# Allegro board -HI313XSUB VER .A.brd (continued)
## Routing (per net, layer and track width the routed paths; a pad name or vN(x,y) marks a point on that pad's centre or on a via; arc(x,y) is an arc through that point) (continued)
VINNQ: length 4.1
  TOP w0.203: 21.16,40.77 21.33,40.6 U25.36
  TOP w0.508: 21.16,40.77 20.82,41.11 20.82,42.76 C299.1 C267.1
VINPQ: length 3.9
  TOP w0.203: U25.35 21.73,41.15
  TOP w0.508: 21.73,41.15 21.48,41.41 21.48,42.85 C300.1 C266.1
3130_AGC: length 2.3
  TOP w0.203: R43.2 94.35,36.77 94.35,36.69 93.93,36.27 U5.7
3130_I2C_SCL: length 29.8
  TOP w0.152: R8.1 80.51,38.63 77.32,38.63 75.68,40.27 75.68,50.99 J7.23
3130_I2C_SDA: length 34.2
  TOP w0.152: J7.24 65.02,61.23 67.11,61.23 67.61,60.72 67.61,59.53 75.98,51.16 75.98,40.4 77.44,38.93 79.72,38.93 R9.1
3130_RSTN: length 26
  TOP w0.152: R30.1 77.58,27.1 67.54,37.15 67.54,40.61 67.03,41.12 65.23,41.12 J7.10
3130_TSI_CLK: length 28.6
  TOP w0.152: J7.19 67.52,55.09 73.55,49.05 73.55,39.94 77.1,36.39 79.85,36.39 80,36.24 C71.2 80.51,35.83 80.52,35.84 RN1.6
3130_TSI_D0: length 43.8
  TOP w0.152: RN3.8 76.16,29.01 67.84,37.32 67.84,40.84 67.51,41.17 67.51,43.2 67.16,43.55 v1(62.2,43.55)
  BOTTOM w0.152: v1(62.2,43.55) 61.36,44.39 61.36,52.22 62.88,53.74 65.3,53.74 J7.17
3130_TSI_D1: length 39.5
  TOP w0.152: v1(62.43,46.12) 67.38,46.12 68.12,45.38 68.12,42.69 68.55,42.26 68.55,38.14 76.55,30.14 80.34,30.14 80.97,29.51 RN3.7
  BOTTOM w0.152: J7.15 65.02,51.48 63.24,51.48 62.43,50.67 v1(62.43,46.12)
3130_TSI_D2: length 30.9
  TOP w0.152: v1(67.99,46.91) 68.45,46.45 68.45,42.79 68.85,42.39 68.85,38.3 76.7,30.45 80.54,30.45 80.97,30.02 RN3.6
  BOTTOM w0.152: J7.16 65.38,48.58 67.2,48.58 67.99,47.8 v1(67.99,46.91)
3130_TSI_D3: length 27.1
  TOP w0.152: RN3.5 80.98,30.53 80.04,31.48 77.15,31.48 69.64,38.98 69.64,42.87 69.23,43.27 69.23,46.98 67.99,48.23 67.26,48.23 J7.13
3130_TSI_D4: length 29.8
  TOP w0.152: J7.14 65.25,48.76 67.99,48.76 69.61,47.14 69.61,43.38 69.94,43.05 69.94,39.13 77.29,31.79 80.47,31.79 80.98,32.31 RN2.7
3130_TSI_D5: length 22.3
  TOP w0.152: RN2.6 77.74,32.82 70.61,39.95 v1(70.61,43.76)
  BOTTOM w0.152: v1(70.61,43.76) 69.44,44.93 J7.11
3130_TSI_D6: length 26
  TOP w0.152: RN2.5 77.66,33.32 71.11,39.87 71.11,44.37 v1(70.55,44.93)
  BOTTOM w0.152: v1(70.55,44.93) 69.39,46.09 65.12,46.09 J7.12
3130_TSI_D7: length 18.8
  TOP w0.152: RN1.8 77.27,34.83 72.23,39.87 72.23,41.04 v1(72.03,41.24)
  BOTTOM w0.152: J7.9 70.88,42.39 v1(72.03,41.24)
3130_TSI_SYNC: length 31.7
  TOP w0.152: RN1.5 81.37,36.35 80.29,37.44 77.52,37.44 74.62,40.33 74.62,49.44 67.63,56.43 65.15,56.43 J7.22
3130_TSI_VALID: length 31.1
  TOP w0.152: RN1.7 80.57,35.34 80.49,35.25 77.29,35.25 72.54,40.01 72.54,48.41 v1(68.59,52.36)
  BOTTOM w0.152: v1(68.59,52.36) 68.59,55.54 J7.21
3136_ADDR0: length 5
  TOP w0.152: U2.39 137.97,38.84 137.97,38.84 137.62,38.84 137.52,38.94 136.85,38.94 136.2,39.59 136.2,41.17 R41.1
3136_ADDR1: length 2.2
  TOP w0.203: U2.38 138.29,39.24 137.86,39.24 137.63,39.47 v1(137.11,39.47)
  BOTTOM w0.381: R103.1 136.85,39.22 v1(137.11,39.47)
3136_DISEQC_IN: length 38.1
  TOP w0.152: R51.1 163.38,43.61 163.05,43.27 R116.1 162.11,42.16 Q6.3 160.54,42.61 159.42,43.73 159.42,45.05 159.06,45.41 156.45,45.41 155.66,44.62 155.66,39.99 154.64,38.97 154.64,33.31 152.12,30.78 149,30.78 146.79,32.99 146.16,32.99 145.17,33.98 145.17,34.68 144.61,35.24 U2.13
3136_DISEQC_OUT: length 32.7
  TOP w0.152: U2.12 143.37,34.36 143.65,34.08 144.56,34.08 146,32.64 146.68,32.64 148.87,30.46 152.24,30.46 v1(155.2,33.42) ; U17.9 162.5,25.07 162.67,25.24 163.23,25.24 163.38,25.09 163.38,24.48 R123.1 v1(163.97,23.08)
  BOTTOM w0.152: v1(155.2,33.42) 163.97,24.66 v1(163.97,23.08)
3136_FUNC_SEL: length 2.8
  TOP w0.152: U2.14 144.85,35.64 R4.1
3136_HV_SEL: length 33
  TOP w0.152: U2.18 145.72,37.24 145.98,37.51 147.86,37.51 148.32,37.05 148.32,32.51 149.42,31.4 151.48,31.4 v1(151.67,31.59) ; v1(163.27,21.76) 163.27,20.05 162.5,19.28 U17.8
  BOTTOM w0.152: v1(151.67,31.59) 155.04,31.59 162.76,23.87 162.76,22.27 v1(163.27,21.76)
3136_I2C_SCL: length 32.3
  TOP w0.152: U2.41 137.42,38.04 137.23,38.23 136.64,38.23 136.18,37.76 R108.2 C221.1 135.47,39.13 135.34,39.26 133.43,39.26 133.08,39.62 133.08,48.18 127.82,53.44 127.82,57.87 125.53,60.17 J3.23
3136_I2C_SDA: length 34.2
  TOP w0.152: U2.40 137.52,38.44 137.38,38.59 136.65,38.59 R104.2 C217.1 135.47,41.17 135.26,41.37 133.64,41.37 133.38,41.62 133.38,48.3 128.13,53.56 128.13,58.11 124.98,61.26 122.49,61.26 J3.24
3136_IOUT_N: length 29.9
  TOP w0.165: U2.32 140.57,40.72 140.68,40.83 140.68,46.59 140.29,46.98 135.12,52.15 135.12,63.11 136.97,64.95 138.39,64.95 C307.2
3136_IOUT_P: length 29.4
  TOP w0.165: U2.31 140.97,46.71 135.42,52.27 135.42,62.99 137.09,64.66 138.38,64.66 C303.2
3136_LNB_EN: length 42.7
  TOP w0.152: U2.21 145.63,38.44 146.24,37.84 148.04,37.84 148.65,37.23 148.65,32.68 149.41,31.92 v1(150.83,31.92) ; U17.5 160.55,17.58 161.24,16.89 163.07,16.89 164.06,17.87 165.23,17.87 165.74,18.38 v1(165.74,21.58)
  BOTTOM w0.152: v1(150.83,31.92) 151.06,32.15 155.02,32.15 163.08,24.1 163.08,22.72 163.83,21.96 165.35,21.96 v1(165.74,21.58)
3136_QOUT_N: length 32.6
  TOP w0.165: C186.2 138.39,67.45 137.47,67.45 133.89,63.87 133.89,51.56 139.32,46.13 139.32,41.03 139.37,40.98 U2.35
3136_QOUT_P: length 33.1
  TOP w0.165: U2.36 138.97,40.98 139.03,41.03 139.03,46.01 133.6,51.43 133.6,64 137.35,67.74 138.39,67.74 C306.2
3136_RF_AGC: length 31.1
  TOP w0.305: R127.2 C37.1 135.14,44.88 134.65,45.36 134.65,48.69 132.36,50.98 132.36,64.58 137.09,69.31 R60.1
3136_RSTN: length 69.1
  TOP w0.152: v1(155.02,49.04) 155.33,48.74 155.33,40.21 154.34,39.22 154.34,33.48 151.94,31.08 149.21,31.08 147.94,32.35 147.94,34.49 147.71,34.72 146.49,34.72 146.31,34.89 R83.1 C38.1 145.8,36.26 145.58,36.04 U2.15
  BOTTOM w0.152: v1(155.02,49.04) 153.7,50.36 132.82,50.36 126.17,43.7 122.71,43.7 J3.10
3136_TS_CLK: length 3.7
  TOP w0.152: R10.2 137.68,36.04 U2.46
3136_TS_OUT0: length 3.8
  TOP w0.152: U2.48 137.87,35.24 R13.2
3136_TS_OUT1: length 3.1
  TOP w0.152: R12.2 137.57,33.24 137.85,33.24 138.97,34.36 U2.1
3136_TS_OUT2: length 2.7
  TOP w0.152: R14.2 138.33,32.98 138.33,33.11 139.37,34.15 139.37,34.24 139.37,34.25 U2.2
3136_TS_OUT3: length 2.4
  TOP w0.152: U2.3 139.77,34.03 138.9,33.16 R16.2
3136_TS_OUT4: length 2.3
  TOP w0.152: R19.2 140.44,33.08 140.44,33.69 140.57,33.83 140.57,34.56 U2.5
3136_TS_OUT5: length 2.1
  TOP w0.152: U2.6 140.97,33.72 140.88,33.63 R20.2
3136_TS_OUT6: length 2.2
  TOP w0.152: U2.8 141.77,33.8 141.94,33.63 141.94,33.62 142.06,33.51 142.06,32.72 R21.2
3136_TS_OUT7: length 2.3
  TOP w0.152: U2.9 142.17,34.15 142.17,34.15 142.17,33.9 142.88,33.19 R25.2
3136_TS_SYNC: length 3
  TOP w0.152: R226.2 136.31,36.77 136.7,37.16 137.74,37.16 137.82,37.24 U2.43
3136_TS_VAL: length 4.2
  TOP w0.152: U2.44 136.89,36.84 135.83,35.78 C176.1 R5.2
3136_TSI_CLK: length 25.7
  TOP w0.152: R10.1 134.29,34.19 134.29,34.24 130.74,37.79 130.74,47.11 125.4,52.45 125.4,53.62 J3.19
3136_TSI_D0: length 24.4
  TOP w0.152: R13.1 134.25,32.84 129.73,37.36 129.73,46.55 123.93,52.34 J3.17
3136_TSI_D1: length 25.9
  TOP w0.152: J3.15 125.78,50.01 129.42,46.37 129.42,37.18 134.35,32.25 135.82,32.25 136.36,31.72 R12.1
3136_TSI_D2: length 29.1
  TOP w0.152: J3.16 122.82,48.58 124.36,48.58 128.38,44.56 128.38,36.75 133.92,31.21 137.37,31.21 R14.1
3136_TSI_D3: length 26.8
  TOP w0.152: R16.1 138.07,30.89 133.75,30.89 128.05,36.59 128.05,44.43 125.02,47.47 J3.13
3136_TSI_D4: length 30.8
  TOP w0.152: R19.1 138.03,29.86 133.31,29.86 127.02,36.15 127.02,43.44 124.42,46.04 122.82,46.04 J3.14
3136_TSI_D5: length 28.5
  TOP w0.152: J3.11 125.1,44.93 126.7,43.33 126.7,36.04 133.21,29.53 138.13,29.53 139.78,31.18 140.34,31.18 R20.1
3136_TSI_D6: length 32.5
  TOP w0.152: J3.12 122.84,43.48 124.37,43.48 125.69,42.16 125.69,35.58 132.76,28.51 138.66,28.51 R21.1
3136_TSI_D7: length 30.1
  TOP w0.152: R25.1 142.3,31.13 141.71,31.13 138.77,28.19 132.61,28.19 125.36,35.44 125.36,41.95 124.93,42.39 J3.9
3136_TSI_SYNC: length 30
  TOP w0.152: J3.22 122.44,58.67 124.47,58.67 126.78,56.36 126.78,53 132.06,47.72 132.06,38.8 134.09,36.77 R226.1
3136_TSI_VALID: length 27.9
  TOP w0.152: R5.1 133.39,36.08 133.39,36.97 131.76,38.6 131.76,47.56 126.45,52.87 126.45,56.2 125.02,57.63 J3.21
3136_XIN: length 12.6
  TOP w0.203: U2.23 144.64,39.24 145.34,39.95 146.16,39.95 146.52,40.3 R24.1
  TOP w0.254: R24.1 147.1,40.35 C172.1 151.11,40.35 151.59,40.83 X6.2
3136_XOUT: length 12.3
  TOP w0.203: U2.22 144.85,38.84 145.5,39.49 R24.2
  TOP w0.254: X6.1 151.59,39.53 151.26,39.86 148.66,39.86 C174.1 147.94,39.49 R24.2
3137_ADDR0: length 3
  TOP w0.203: U25.40 19.97,38.18 19.6,38.55 19.06,38.55
  TOP w0.381: R209.1 18.68,38.93 19.06,38.55
3137_ADDR1: length 3
  TOP w0.203: U25.38 20.21,38.98 19.71,39.48 19.71,39.71
  TOP w0.381: R208.1 19.71,40.57 19.71,39.71
3137_FUNC_SEL: length 2.4
  TOP w0.203: U25.14 26.86,35.38 27.33,34.92 27.76,34.92 28.03,34.64 R205.1
3137_I2C_SCL: length 28.3
  TOP w0.152: J4.23 14.95,54.27 14.95,36.82 v1(15.41,36.37) 15.89,35.88 R81.1
  BOTTOM w0.152: v1(15.41,36.37) 15.63,36.37 R81.1
3137_I2C_SDA: length 31.5
  TOP w0.152: J4.24 7.61,61.26 9.41,61.26 10.31,60.36 10.31,59.39 15.25,54.45 15.25,37.28 v1(15.46,37.08) 15.63,36.9 R80.1
  BOTTOM w0.152: v1(15.46,37.08) 15.43,37.08 15.61,36.9 R207.2
3137_IF_AGC: length 23.3
  TOP w0.305: R196.1 18.84,63.98 15.41,60.55 15.41,55.49 16.93,53.97 C268.1 16.93,45.88 16.99,45.81 16.99,44.58 R199.2
3137_RSTN: length 51.9
  TOP w0.203: U25.15 26.97,35.78 27.47,35.27 29.88,35.27 30.49,34.66 v1(30.49,34.41) ; J4.10 4.53,40.4 4.53,29.89 5.17,29.25 R198.1 6.54,29.25 6.55,29.24 C340.1 7.7,29.24 v1(8.57,28.37)
  BOTTOM w0.203: v1(30.49,34.41) 30.49,28.09 29.6,27.2 9.74,27.2 v1(8.57,28.37)
3137_TSI_CLK: length 27.9
  TOP w0.152: R133.1 17.26,31.13 13.32,35.07 13.32,50.82 J4.19
3137_TSI_D0: length 27.6
  TOP w0.152: J4.17 12.31,49.29 12.31,34.61 16.3,30.63 18.3,30.63 R134.1
3137_TSI_D1: length 26.6
  TOP w0.152: R165.1 18.99,30.32 16.16,30.32 12,34.48 12,47.06 J4.15
3137_TSI_D2: length 30.2
  TOP w0.152: R227.1 19.67,30.02 16,30.02 11.68,34.33 11.68,46.54 9.36,48.86 7.66,48.86 J4.16
3137_TSI_D3: length 27.1
  TOP w0.152: J4.13 11.35,45.17 11.35,34.2 15.85,29.7 20.32,29.7 R228.1
3137_TSI_D4: length 30.9
  TOP w0.152: J4.14 7.84,46.15 9.93,46.15 11.03,45.05 11.03,34.06 15.72,29.37 20.96,29.37 R230.1
3137_TSI_D5: length 27.5
  TOP w0.152: R231.1 21.59,29.06 15.57,29.06 10.71,33.92 10.71,43.27 J4.11
3137_TSI_D6: length 31
  TOP w0.152: R232.1 22.23,28.73 15.45,28.73 10.4,33.78 10.4,42.56 9.34,43.63 8.85,43.63 7.56,44.93 J4.12
3137_TSI_D7: length 28
  TOP w0.152: R233.1 22.87,28.42 15.32,28.42 10.1,33.63 10.1,41.34 J4.9
3137_TSI_SYNC: length 31.8
  TOP w0.152: J4.22 7.56,58.67 10.01,58.67 14.64,54.03 14.64,36.06 16.75,33.95 R128.1
3137_TSI_VALID: length 28.9
  TOP w0.152: J4.21 10.54,57.63 14.34,53.83 14.34,35.73 R132.1
3137_XIN: length 27.6
  TOP w0.203: R164.2 29.15,40.23 28.46,39.54 27.45,39.54 26.88,38.98 U25.23
  TOP w0.254: R47.1 30.62,43.78 29.88,43.05 R164.2 30.77,40.23 C325.2 34.18,40.35 34.96,41.14 X3.2
3137_XOUT: length 12.4
  TOP w0.203: U25.22 26.99,38.58 27.57,39.16 28.72,39.16 28.97,39.41 R164.1
  TOP w0.254: X3.1 34.96,38.53 34.15,39.34 C322.2 30.82,39.41 R164.1
18250B_SCL_T: length 34.3
  TOP w0.152: v1(93.91,54.63) 93.52,54.23 93.52,50.77 99.03,45.26 99.03,34.36 98.36,33.69 R27.2 ; R39.2 R45.1 v1(85.96,54.27)
  BOTTOM w0.152: v1(85.96,54.27) 92.12,54.27 92.35,54.04 93.33,54.04 v1(93.91,54.63)
18250B_SDA_T: length 32.7
  TOP w0.152: v1(85,54.3) R46.1 R40.2 ; v1(92.9,54.63) 93.16,54.37 93.16,50.69 98.72,45.13 98.72,35.27 98.4,34.96 R26.2
  BOTTOM w0.152: v1(92.9,54.63) 86.61,54.63 86.43,54.81 85.5,54.81 v1(85,54.3)
AC2012_SCL_T: length 25.2
  TOP w0.152: R61.2 136.55,59.16 136.55,52.7 143.16,46.09 143.16,44.21 R65.2 142.91,42.38 142.57,42.04 U2.27
AC2012_SDA_T: length 24.3
  TOP w0.152: R62.2 138.12,60.29 136.86,59.03 136.86,52.83 143.47,46.22 143.47,42.99 R66.2 143.42,42.44 142.97,41.99 U2.26
ANT_CTRL/LOCK: length 48
  TOP w0.203: R224.2 R150.2 51.41,52.59 51.41,35.76 v1(51.26,35.6) ; U25.16 27.07,36.18 27.6,35.65 30.14,35.65 33.94,31.85 36.24,31.85 37.89,33.5 v1(46.27,33.5)
  BOTTOM w0.203: v1(51.26,35.6) 49.15,33.5 v1(46.27,33.5)
ANT_POWER: length 22.7
  TOP w0.508: Q11.3 50.23,70.22 R157.2 44.64,72.1 42.33,74.42 C279.1 41.09,79.44 40.68,79.85 36.49,79.85 L13.2
CLK_TU_OUT: length 1.2
  TOP w0.254: R47.2 30.62,55.49 C330.2
DEMO_VIN: length 19.5
  TOP w0.178: U5.12 91.68,38.46 91.61,38.53 91.61,39.16 92.68,40.23 92.68,48.23 89.76,51.15 89.76,54.08 C50.1 89.73,54.8 89.73,55.02 R7.2
DEMO_VIP: length 19.4
  TOP w0.178: U5.13 91.28,38.51 91.31,38.54 91.31,39.29 92.37,40.35 92.37,48.1 89.45,51.02 89.45,54.09 C51.1 89.43,54.74 89.43,55.05 R11.2
I2C_SCL_3130: length 7.3
  TOP w0.152: U5.20 88.48,38.38 87.94,38.91 84.44,38.91 84.31,39.05 C84.1 R23.2 82.28,39.05 82.26,39.06 R8.2
I2C_SDA_3130: length 8.2
  TOP w0.152: R9.2 82.26,40.15 82.28,40.14 R22.2 C72.1 84.65,39.29 88.02,39.29 88.88,38.44 U5.19
IF_OUTN: length 18.8
  TOP w0.508: C335.2 20.64,61.18 19.93,60.47 19.93,51.38 21.45,49.85 21.45,44.8 C266.2
IF_OUTP: length 20
  TOP w0.508: C267.2 20.79,44.82 20.79,49.58 19.25,51.12 19.25,60.75 20.57,62.07 C337.2
LNB_PWR: length 76.8
  TOP w0.381: D27.1 C170.1 C58.1 C104.1 157.98,68.04 157.98,68.93 156.62,68.93 156.62,69.69 157.98,69.69 157.98,70.45 C78.1 155.72,75.58 154.96,75.58 154.96,71.6 154.17,71.6 154.17,75.58 153.41,75.58 153.41,71.6 151.58,71.6 C64.1
  TOP w0.457: D27.1 165.21,66.51 168.56,63.16 168.56,42.59 168.08,42.11 C155.2 D17.2
  TOP w0.508: J16.2 C64.1
LNB_PWR_B: length 52.2
  TOP w0.381: R166.2 138.98,79.22 140.87,79.22 140.87,74.01 141.63,74.01 141.63,81.55 143.6,81.55 C166.1 143.6,76.49 146.43,76.49 C288.1 C287.1 157.5,79.82 159.8,77.52 159.8,70.01 160.4,69.42 D27.2
LOOPTHROUGH: length 8
  TOP w0.381: J16.1 136.6,77.67 R166.1
  TOP w0.508: C283.1 J16.1
LT: length 4.3
  TOP w0.254: 88.77,66.6 U4.3
  TOP w0.483: C66.2 88.77,66.6
MXL603_SCL: length 18.1
  TOP w0.152: R143.2 27.55,54.11 R213.2 27.75,53.88 27.75,52.67 28.08,52.34 28.08,48.71 v1(27.34,47.97) ; U25.26 25.33,40.5 25.52,40.68 26,40.68 26.07,40.61 27.09,40.61 27.34,40.86 27.34,44.29 v1(26.33,45.31)
  BOTTOM w0.152: v1(27.34,47.97) 26.33,46.96 v1(26.33,45.31)
MXL603_SDA: length 17.6
  TOP w0.152: v1(28.11,47.97) 28.39,48.25 28.39,52.5 28.06,52.83 28.06,53.71 R211.2 R137.2 ; U25.24 26.78,39.38 27.47,40.07 27.47,40.48 27.73,40.73 27.73,44.42 26.84,45.31 v1(26.84,45.94)
  BOTTOM w0.152: v1(26.84,45.94) 26.84,46.7 v1(28.11,47.97)
REG2OUT: length 41.4
  TOP w0.203: U34.2 147.16,69.12 147.96,69.92 148.49,69.92 148.49,68.93 148.06,68.5 U34.1 ; v1(143.16,66.69) 143.39,66.93 U34.10 ; U34.25 149.18,66.53 C225.2 ; C414.1 144.68,70.4 145.96,69.13 U34.5
  TOP w0.254: v1(152.3,66.26) 150.97,66.26 C225.2 ; C414.1 144.23,70.48 v1(144,70.71)
  TOP w0.381: 148.49,69.92 C130.1 152.33,69.92 154.33,67.91 v1(154.33,66.13)
  BOTTOM w0.381: v1(154.33,66.13) 154.21,66.26 v1(152.3,66.26) 150.28,64.24 143.82,64.24 143.16,64.91 143.16,65.78 C131.1 143.16,65.8 v1(143.16,66.69) 142.25,67.6 142.25,68.96 v1(144,70.71)
RESET_TUNER: length 31.7
  TOP w0.152: v1(27.8,37.3) 27.8,37.35 27.77,37.38 U25.19 ; 24.42,51.36 C302.1 22.58,51.36 21.68,52.27 21.68,58.57 22.26,59.15 23.53,59.15 24.81,60.42 U20.10 ; 24.42,51.36 24.42,49.24 28.13,45.54 v1(28.13,40.1) ; 24.42,51.36 R225.2
  BOTTOM w0.152: v1(27.8,37.3) 28.26,37.76 28.26,39.97 v1(28.13,40.1)
RF_IN_18250B: length 3.1
  TOP w0.483: J1.2 C56.1
RF_IN_T: length 3.8
  TOP w0.5: C331.1 L13.1 38.38,77.69 J2.2
RF_OUT_18250B: length 5.4
  TOP w0.483: C79.1 81.19,77.41 arc(80.89,77.61) 80.53,77.69 J1.1
RF_OUT_T: length 1.7
  TOP w0.5: J2.1 23.41,77.67 C333.1
RFIN: length 2.4
  TOP w0.254: 89.9,66.59 89.27,65.96 U4.2
  TOP w0.483: 89.9,66.59 90.58,67.28 C65.2
TS_RSTN_DEMO: length 13.9
  TOP w0.152: U5.37 90.88,31.97 90.91,31.93 C53.1 91.05,31.29 91.12,31.29 91.42,30.99 91.42,29.69 89.59,27.86 85,27.86 84.23,27.1 R37.2 R30.2
$3N275: length 5.2
  TOP w0.203: U2.37 138,39.64 137.63,40.01
  TOP w0.305: R127.1 R69.2 137.35,42.46 137.35,40.29 137.63,40.01
$3N304: length 3.6
  TOP w0.203: C226.1 145.4,41.65 144.7,40.95 144.7,39.96 144.39,39.64 U2.24
$3N444: length 3.2
  TOP w0.381: R68.2 138.82,17.11
  vias: v1(137.73,20.28) v1(137.68,19.21) v1(137.8,23.79) v1(137.8,22.75) v1(137.78,21.58) v1(139.83,21.58) v1(139.83,20.31) v1(139.83,19.19) v1(139.86,23.79) v1(139.86,22.75) v1(142.07,23.81) v1(142.07,22.8) v1(142.07,21.55) v1(142.07,20.28) v1(142.07,19.14)
$3N446: length 3.3
  TOP w0.381: R68.1 R141.1 U12.1
$4N322: length 3.8
  TOP w0.203: U34.27 149.85,67.33 C487.2 150.06,66.93 U34.26
$4N324: length 3.1
  TOP w0.203: C168.2 149.51,64.93 149.51,65.63 149.01,66.13 U34.24
$4N325: length 9.3
  TOP w0.203: 148.33,65.02 U34.22 ; U34.21 147.56,63.51 147.69,63.38 C194.1 147.39,62.27 147.16,62.5 U34.20
  TOP w0.254: 148.33,65.02 148.33,63.37 148.74,62.96 C190.1
  TOP w0.381: C194.1 148.74,62.27 C190.1
$4N326: length 8
  TOP w0.152: U34.15 145.16,64.19 144.32,63.36 143.71,63.36 C538.1 141.91,62.06 141.77,62.2 139.89,62.2 139.77,62.07 R61.1
$4N327: length 9.7
  TOP w0.152: U34.16 145.56,64.08 144.51,63.04 143.85,63.04 142.78,61.97 142.78,60.66 142.42,60.29 C534.1 141.91,60.79 141.77,60.93 139.89,60.93 139.77,60.8 R62.1
$4N328: length 3.2
  TOP w0.152: R72.1 144.56,62.66 144.76,62.66 145.96,63.85 U34.17
$4N329: length 12.1
  TOP w0.203: U34.18 146.36,63.68 145.32,62.64 C532.1
  TOP w0.254: C532.1 145.31,62.2 144.81,62.2 144.68,62.07 144.68,57.75 143.41,56.48 X4.1
$4N330: length 12.2
  TOP w0.203: U34.19 146.76,63.51 146.33,63.09 C531.1
  TOP w0.254: C531.1 146.81,62.22 146.97,62.07 146.97,56.86 147.35,56.48 X4.2
$4N331: length 4.1
  TOP w0.152: R59.1 142.52,62.83 143.9,64.21 143.9,65.22 144.01,65.33 U34.14
$4N332: length 6.7
  TOP w0.152: R64.1 139.75,63.36 139.86,63.47 142.65,63.47 143.57,64.39 143.57,65.38 143.92,65.73 U34.13
$4N333: length 6.3
  TOP w0.165: C303.1 139.75,64.12 140.27,64.64 141.46,64.64 141.91,64.19 C537.1 142.35,64.54 142.35,64.55 142.48,64.67 142.85,64.67 143.24,65.07 143.24,65.63 143.77,66.16 143.85,66.16 143.88,66.13 U34.12
$4N334: length 6.3
  TOP w0.165: C307.1 140.32,64.93 141.42,64.93 141.91,65.42 C241.1 142.44,64.97 142.72,64.97 142.95,65.19 142.95,65.75 143.65,66.45 143.85,66.45 143.92,66.53 U34.11
$4N336: length 5.4
  TOP w0.165: C186.1 140.31,67.46 141.44,67.46 141.91,66.98 C535.1 142.39,67.38 143.53,67.38 143.59,67.33 U34.9
$4N337: length 5.4
  TOP w0.165: C306.1 139.75,68.28 140.28,67.75 141.45,67.75 141.91,68.21 C536.1 142.53,67.67 143.53,67.67 143.59,67.73 U34.8
$4N338: length 5
  TOP w0.203: 146.76,69.69 U34.3
  TOP w0.508: L1.2 146.76,72.43 R63.1 146.76,69.69
$4N360: length 1.1
  TOP w0.508: C304.2 146.76,74.33 R63.2
$4N368: length 2.9
  TOP w0.508: C64.2 C305.2 L1.1
$4N406: length 4.7
  TOP w0.152: C148.1 145.29,71.85 145.29,70.33 146.36,69.27 U34.4
$4N416: length 8.1
  TOP w0.152: v1(144.89,69.44) 145.07,69.44 145.56,68.95 U34.6
  TOP w0.305: v1(143.44,68.6) 142.73,69.31 C545.1 141.91,69.81 141.77,69.94 140.09,69.94 139.75,69.61 R60.2
  BOTTOM w0.305: v1(143.44,68.6) 143.78,68.94 144.28,69.44 v1(144.89,69.44)
$4N439: length 3.9
  TOP w0.381: R112.1 166.25,60.93 R2.1 166.96,59.56 166.48,59.07 U14.1
$4N597: length 4.6
  TOP w0.508: C283.2 L16.2 C282.1
$4N600: length 4.7
  TOP w0.203: U34.7 144.94,68.5 arc(144.74,68.54) 144.57,68.65 144.43,68.8
  TOP w0.508: C282.2 142.8,71.48 arc(142.99,70.51) 143.54,69.68 144.43,68.8
$4N809: length 4
  TOP w0.305: C171.2 156.39,17.48 158.24,17.48 158.6,17.84 U17.2
$4N822: length 3.5
  TOP w0.152: C163.2 C175.2 159.98,17.16 159.9,17.25 U17.4
$4N827: length 1
  TOP w0.152: R102.2 C175.1
$4N836: length 4.8
  TOP w0.152: U17.6 161.2,17.58 161.56,17.21 162.94,17.21 163.56,17.83 163.56,18.13 R117.2
$4N838: length 4.5
  TOP w0.152: U17.7 161.85,17.76 162.03,17.57 162.84,17.57 163.07,17.8 163.07,18.7 R121.2
$4N849: length 2
  TOP w0.254: U17.14 159.25,26.2 C139.1
$4N898: length 4.1
  TOP w0.152: R92.1 163.43,25.85 161.7,25.85 161.2,25.34 U17.11
$4N900: length 3.4
  TOP w0.152: C246.1 163.7,25.55 162.03,25.55 161.85,25.36 U17.10
$4N922: length 3.2
  TOP w0.381: R114.1 R51.2 162.85,45.08 Q6.1
$4N925: length 3.6
  TOP w0.381: R35.2 167.11,45.05 165.77,43.71 R114.2 165.64,43.48 C155.1
$5N739: length 4
  TOP w0.381: U21.1 39.56,31.08 R18.1 R50.1
$5N778: length 7.2
  TOP w0.203: 19.17,39.49 20.08,38.58 U25.39
  TOP w0.381: 19.17,39.49 19.17,40.05 18.43,40.79 R216.2 R199.1
$5N783: length 3.8
  TOP w0.152: U25.47 20.26,35.38 18.46,33.57 18.46,33.5 R132.2
$5N784: length 4.3
  TOP w0.152: U25.48 20.43,34.98 18.88,33.43 18.88,33 R133.2
$5N786: length 3.5
  TOP w0.152: U25.46 20.2,35.78 18.38,33.95 R128.2
$5N788: length 4.3
  TOP w0.152: R81.2 17.44,35.88 17.57,35.76 C298.1 18.41,36.19 18.43,36.19 19.17,36.93 20.08,36.93 20.13,36.98 U25.43
$5N863: length 4.1
  TOP w0.152: R134.2 19.72,32.86 20.69,32.86 21.73,33.91 U25.2
$5N867: length 3
  TOP w0.203: U25.32 22.93,41.57
  TOP w0.607: 22.93,41.57 22.93,41.91 23.25,42.23 R204.1
$5N880: length 4.3
  TOP w0.381: R197.1 C345.2 47.11,37.53 v1(46.9,37.74) U18.4
  BOTTOM w0.381: R79.2 47.7,37.74 v1(46.9,37.74)
$5N881: length 2.7
  TOP w0.381: C345.1 47.79,39.58 C224.1
  BOTTOM w0.381: v1(46.7,39.44) R79.1
$5N882: length 24.4
  TOP w0.508: R222.2 41.06,46.45 v1(41.57,46.96)
  BOTTOM w0.381: R201.1 24.54,42.37 26.59,42.37 28.36,44.14 28.36,45.81 32.45,49.9 40.15,49.9 41.57,48.48 v1(41.57,46.96)
$5N900: length 4
  TOP w0.152: R80.2 17.41,36.9 17.59,36.72 C295.1 18.53,36.72 19.06,37.26 19.95,37.26 20.07,37.38 U25.42
$5N935: length 3.5
  TOP w0.152: U25.3 22.13,33.87 20.79,32.53 20.38,32.53 R165.2
$5N944: length 3.1
  TOP w0.152: R227.2 21.22,32.38 21.22,32.53 22.53,33.84 U25.4
$5N946: length 2.8
  TOP w0.152: U25.5 22.93,33.81 21.76,32.63 R228.2
$5N948: length 2.6
  TOP w0.152: R230.2 22.72,33.17 23.33,33.78 U25.6
$5N950: length 2.5
  TOP w0.152: R231.2 24.13,32.42 U25.8
$5N952: length 2.4
  TOP w0.152: U25.9 24.53,32.55 24.63,32.45 R232.2
$5N954: length 2.6
  TOP w0.152: R233.2 24.93,32.6 U25.10
$6N450: length 3.1
  TOP w0.152: Q12.1 v1(50.97,64.33)
  BOTTOM w0.381: R217.1 51.09,64.46 v1(50.97,64.33) 50.94,64.31 R162.2
$6N451: length 5.9
  TOP w0.381: v1(51.09,69.06) 51.22,68.93 Q11.2 51.42,67.71 R200.2
  BOTTOM w0.381: R217.2 v1(51.09,69.06)
$6N454: length 3.2
  TOP w0.152: U20.17 27.97,57.49 28.44,57.02 C252.1 R137.1
$6N455: length 3
  TOP w0.152: U20.16 27.47,56.82 C253.1 R143.1
$6N457: length 12.7
  TOP w0.203: U20.19 29.51,59.42 30.69,58.24 32.58,58.24 32.93,58.59 35.33,58.59 C326.1 38.46,58.58 39.28,57.75 X5.2
$6N458: length 3.7
  TOP w0.5: 28.28,75.93 28.27,75.91 L11.1 ; 28.28,75.93 28.3,75.94 C338.1 arc(28.39,77.28) R167.2 L10.2 ; 28.28,75.93 R169.1
$6N459: length 1.8
  TOP w0.5: L14.1 R169.2 28.27,75.13 L11.2
$6N460: length 2.7
  TOP w0.5: C332.1 32.42,77.69 D1.3 32.68,77.69 C331.2
$6N461: length 1
  TOP w0.5: C338.2 27.48,77.79 L12.1
$6N463: length 3.7
  TOP w0.381: Q11.1 v1(49.19,69.06)
  BOTTOM w0.381: R214.2 49.82,68.42 v1(49.19,69.06)
$6N464: length 1.7
  TOP w0.203: R224.1 48.93,54.98 Q10.1
$6N465: length 1.1
  TOP w0.5: C329.2 R170.1
$6N466: length 3.2
  TOP w0.152: C294.2 31.41,63.09 29.75,61.42 U20.23
$6N467: length 2.7
  TOP w0.254: C330.1 30.14,56.86 28.47,58.54 U20.18
$6N468: length 5.3
  TOP w0.254: R196.2 21.81,63.98 21.83,63.95 C285.1 23.33,63.95 24.24,63.04 25.76,63.04 25.97,62.83 U20.6
$6N470: length 3.8
  TOP w0.254: v1(27.03,64.61) C318.2 ; U20.2 27.97,63.46 v1(28.23,63.72)
  BOTTOM w0.254: v1(28.23,63.72) 27.46,64.5 arc(27.33,64.58) 27.19,64.61 v1(27.03,64.61)
$6N471: length 3.3
  TOP w0.254: C321.2 28.42,65.45 arc(28.33,64.97) 28.05,64.56 27.84,64.34 arc(27.56,63.93) 27.47,63.45 U20.3
$6N487: length 1.8
  TOP w0.5: L10.1 29.45,77.72 R167.1 C332.2
$6N488: length 3
  TOP w0.5: C329.1 D2.3 C333.2
$6N491: length 14.9
  TOP w0.254: U20.24 29.44,61.92 arc(29.6,61.95) 29.73,62.04 29.87,62.19 arc(30.07,62.48) 30.14,62.83 30.14,63.14
  TOP w0.5: 30.14,63.14 v1(30.14,70.2) ; R170.2 v1(25.19,70.2)
  BOTTOM w0.5: v1(25.19,70.2) v1(30.14,70.2)
$6N492: length 17
  TOP w0.203: U20.20 29.54,59.92 30.87,58.6 32.25,58.6 33.16,59.51 C327.1 38.49,59.51 39.28,60.29 X5.1
$6N503: length 6.4
  TOP w0.508: v1(49.95,64.36) Q12.3 Q10.3
  BOTTOM w0.381: v1(49.95,64.36) 49.82,64.48 R214.1
$6N504: length 2.6
  TOP w0.254: C337.1 22.94,61.92 U20.7
$6N505: length 2.7
  TOP w0.254: C335.1 23.05,61.44 25.33,61.44 U20.8
$6N513: length 3
  TOP w0.254: U20.9 24.67,60.92 23.53,59.78 R192.1
$6N515: length 3.5
  TOP w0.254: U20.12 25.08,59.42 24.65,59 C290.1
  TOP w0.381: C290.1 24.4,57.38 LB2.1
$6N592: length 2.3
  TOP w0.5: L14.2 C346.2 28.3,71.66 28.21,71.57 28.22,71.56 Z1.3
$6N593: length 2.4
  TOP w0.5: Z1.2 28.18,69.18 R195.1 28.18,67.2 C321.1
$6N594: length 1.4
  TOP w0.483: Z1.4 27.37,71.55 27.39,71.57 27.39,72.56 R171.1
$6N595: length 2.4
  TOP w0.483: 27.37,69.19 27.37,69.22 Z1.1
  TOP w0.5: 27.37,69.19 R195.2 27.37,67.3 C318.1
$7N202: length 3.3
  TOP w0.381: R17.1 R32.1 77.65,51.08 U3.1
$7N218: length 3.9
  TOP w0.152: R26.1 95.78,34.46 93.49,34.46 93.28,34.67 U5.3
$7N219: length 3.9
  TOP w0.152: U5.2 93.25,34.27 93.39,34.13 95.83,34.13 R27.1
$7N227: length 5.9
  TOP w0.152: U5.25 87.33,35.87 86.69,35.23 84.31,35.23 83.69,35.84 RN1.3
$7N228: length 5.9
  TOP w0.152: U5.22 87.5,37.07 87.18,37.39 84.43,37.39 83.39,36.35 RN1.4
$7N237: length 4.2
  TOP w0.381: 79.7,46.99 R17.2
$7N362: length 4.3
  TOP w0.203: R6.1 93.68,30.66 R31.2 93.67,30.9 92.08,32.49 U5.40
$7N366: length 10.5
  TOP w0.203: U5.39 91.68,32.39 92.86,31.21 R31.1 93.12,30.41 93.12,28.76 C62.1 93.76,28.12 93.76,26.37 92.95,25.56 X1.2
$7N370: length 6
  TOP w0.203: R6.2 C63.1 94.5,28.61 94.14,28.25 94.14,26.37 94.95,25.56 X1.1
$7N391: length 6
  TOP w0.152: RN2.2 83.07,32.31 83.24,32.48 86.13,32.48 87.52,33.87 U5.30
$7N393: length 6
  TOP w0.152: U5.29 87.49,34.27 86.04,32.82 RN2.3
$7N395: length 5.9
  TOP w0.152: RN2.4 86.09,33.32 87.44,34.67 U5.28
$7N397: length 5.8
  TOP w0.152: U5.27 87.4,35.07 86.79,34.47 83.66,34.47 83.29,34.83 RN1.1
$7N399: length 5.8
  TOP w0.152: U5.26 87.37,35.47 86.74,34.85 84.06,34.85 83.57,35.34 RN1.2
$7N402: length 7.3
  TOP w0.152: RN3.4 86.09,30.53 87.87,32.31 87.87,32.5 88.48,33.11 U5.31
$7N404: length 8
  TOP w0.152: U5.32 88.88,32.95 88.2,32.27 88.2,32.08 86.14,30.02 RN3.3
$7N406: length 10.2
  TOP w0.152: U5.34 89.68,32.68 89.45,32.45 89.45,31.99 89.26,31.8 89.26,30.31 88.47,29.51 RN3.2
$7N408: length 11.7
  TOP w0.152: RN3.1 89.42,29.01 90.39,29.98 90.39,31.79 90.57,31.97 90.57,32.56 90.48,32.65 U5.36
$8N5: length 4.2
  TOP w0.483: C48.2 R34.2 90.61,71.75 90.61,70.66 R15.1 C40.1 C6.1
$8N73: length 4.2
  TOP w0.483: C40.2 R15.2 90.61,69.84 C65.1 D3.3
$8N179: length 3.8
  TOP w0.381: R42.1 104.41,35.32 104.23,35.5 R1.1 U1.1
$8N211: length 1.7
  TOP w0.254: U4.30 91.32,63.74
  TOP w0.381: C30.2 92.15,63.74 91.32,63.74
$8N230: length 4.3
  TOP w0.203: U4.26 90.95,61.74 91.24,61.44 91.24,60.42 C31.1
  TOP w0.305: C31.1 R33.1
$8N237: length 24.3
  TOP w0.305: R33.2 92.01,57.35 92.01,50.17 97.2,44.98 97.2,37.56 96.63,36.99 C32.1 R43.1
$8N249: length 1.8
  TOP w0.178: C35.1 89.67,59.3 89.67,59.76 89.77,59.85 U4.24
$8N251: length 1.7
  TOP w0.178: C39.1 89.37,59.13 89.37,59.75 89.27,59.85 U4.23
$8N253: length 2.5
  TOP w0.178: R7.1 89.76,56.55 89.76,56.8 C59.2 90.1,57.14 89.76,57.49 89.76,57.82 C35.2
$8N255: length 2.5
  TOP w0.178: R11.1 89.45,56.52 89.45,56.8 C61.1 89.11,57.14 89.45,57.49 89.45,57.82 C39.2
$8N297: length 5.4
  TOP w0.152: R39.1 C82.1 85.96,58.87 86.42,59.33 87.61,59.33 88.27,59.99 U4.21
$8N299: length 5.6
  TOP w0.152: R40.1 C83.1 85,58.54 86.16,59.71 87.52,59.71 87.77,59.96 U4.20
$8N324: length 2.8
  TOP w0.254: C69.1 82.77,63.24 C2.1 83.82,63.24 U4.12
$8N326: length 3
  TOP w0.254: C70.1 82.86,62.42 C2.2 84.2,62.42 84.52,62.74 U4.13
$8N328: length 7.9
  TOP w0.254: X2.1 78.1,63.61 78.6,63.11 81.72,63.11 C69.2
$8N330: length 8.3
  TOP w0.254: X2.2 78.1,62.01 78.57,62.48 81.69,62.48 C70.2
$8N351: length 4.1
  TOP w0.254: U4.9 84.88,64.74 84.14,65.48 R44.1 82.85,65.48 C76.1 R38.1
$8N354: length 1
  TOP w0.254: R38.2 C44.1
$8N359: length 3
  TOP w0.254: U4.10 84.74,64.24 84.31,64.66 R44.2 82.79,64.66 C77.1
$8N375: length 2.5
  TOP w0.254: U4.8 86.27,65.8 85.96,66.11 85.76,66.31
  TOP w0.381: C41.1 85,66.31 85.76,66.31
$8N396: length 1.1
  TOP w0.483: C6.2 L2.1
$8N403: length 4.5
  TOP w0.483: C85.1 C48.1 R34.1 90.61,72.56 89.64,73.53 C3.2
$8N409: length 1.1
  TOP w0.483: L3.1 C85.2
$8N416: length 3.8
  TOP w0.483: R36.1 89.57,74.61 arc(89.68,74.68) 89.8,74.71 C28.1 ; R36.1 C3.1 ; R36.1 88.71,74.47 arc(88.59,74.64) 88.55,74.84 C49.2
$8N419: length 1.2
  TOP w0.483: C28.2 L15.1
$8N429: length 2.1
  TOP w0.483: C52.2 C49.1 C29.1
$8N432: length 1.2
  TOP w0.483: C29.2 L17.1
$8N437: length 1.2
  TOP w0.483: L4.1 C27.2
$8N439: length 2.3
  TOP w0.483: C80.2 88.55,79.11 C52.1 C27.1
$8N444: length 2.3
  TOP w0.483: L5.1 C56.2 C80.1
$8N472: length 6
  TOP w0.483: C66.1 87.43,71.18 L8.1 87.41,71.19 D4.3 85.69,72.91 85.69,72.91 C79.2

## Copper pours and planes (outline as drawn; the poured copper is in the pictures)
1V1_VDD_T on TOP (solid shape): 40.43,47.08 40.43,45.56 40.3,45.43 39.03,45.43 38.9,45.56 38.9,47.08 39.03,47.21 40.3,47.21
1V1_VDD_T on BOTTOM (solid shape): outline of 108 points within 17.82,31.72 40.3,48.74
1V2_DVDD_S on TOP (solid shape): 132.88,25.24 132.88,23.49 132.82,23.44 131.89,23.44 131.68,23.64 130.49,23.64 130.41,23.72 130.41,25.22 130.56,25.37 132.75,25.37
1V2_DVDD_S on BOTTOM (solid shape): outline of 104 points within 130.41,24.78 148.61,41.56
1V8_T on TOP (solid shape): 51.35,34.51 51.35,28.67 49.7,27.02 47.66,27.02 46.52,28.16 41.31,28.16 41.19,28.29 41.19,29.3 41.31,29.43 46.39,29.43 47.41,30.45 49.19,30.45 49.95,31.21 49.95,34.51 50.08,34.64 51.22,34.64
3V3_C on TOP (solid shape): 104.05,50.05 104.05,46.67 104.06,46.66 104.06,46.01 104.9,45.18 107.46,45.18 107.66,44.98 107.66,43.1 106.52,41.95 106.52,36.26 106.32,36.06 105.43,36.06 105.2,36.29 105.2,39.06 104.97,39.29 100.17,39.29 100.09,39.36 100.09,40.86 100.21,40.98 104.07,40.98 104.36,41.27 104.36,42.61 101.72,45.26 101.72,47.44 100.96,48.2 97.61,48.2 97.38,48.44 97.38,49.49 100.62,49.49 100.62,49.87 100.24,49.87 100.24,49.49 99.99,49.49 99.99,49.87 99.61,49.87 99.61,49.49 99.35,49.49 99.35,49.87 98.97,49.87 98.97,49.49 98.72,49.49 98.72,49.87 98.34,49.87 98.34,49.49 97.38,49.49 97.38,50.12 97.55,50.3 103.8,50.3
3V3_DVDD_S on TOP (solid shape): 145.19,32.66 145.19,32.28 145.02,32.1 145.02,28.92 144.99,28.9 144,28.9 143.9,29 143.9,32.66 144.03,32.78 145.07,32.78
3V3_DVDD_S on BOTTOM (solid shape): outline of 109 points within 133.69,32.17 146.39,40.06
3V3_DVDD_T on TOP (solid shape): 29.63,31.08 33.08,31.08 33.31,30.85 33.31,30.19 33.19,30.07 28.23,30.07 26.05,32.25 26.05,32.4 25.9,32.4 25.57,32.73 25.57,33.37 25.91,33.72 26.09,33.72 26.09,33.89 26.33,34.13 26.58,34.13
3V3_DVDD_T on BOTTOM (solid shape): outline of 88 points within 19.22,33.11 27.98,40.48
3V3_MOS_C on TOP (solid shape): 78.88,45.07 78.88,41.74 78.82,41.74 78.82,40.21 78.48,39.88 77.38,39.88 76.63,40.63 76.63,45.04 76.73,45.15 78.8,45.15
3V3_MOS_C on TOP (solid shape): 102.05,37.92 102.05,22.93 98.93,19.81 80.46,19.81 70.55,29.71 69.44,29.71 69.18,29.97 69.18,31.34 69.51,31.67 70.78,31.67 79.67,22.78 80.99,22.78 81.07,22.7 81.07,21.86 81.35,21.58 97.91,21.58 100.07,23.74 100.07,37.92 100.2,38.04 101.92,38.04
3V3_MOS_C on BOTTOM (solid shape): 77.41,41.73 77.41,36.24 71.98,30.8 69.46,30.8 69.45,30.81 69.09,30.81 68.45,31.45 68.45,34.51 66.67,36.29 66.04,36.29 65.53,36.8 65.53,37.69 66.04,38.19 66.8,38.19 69.98,35.02 69.98,32.4 70.23,32.15 71.37,32.15 75.94,36.72 75.94,41.78 76.14,41.98 77.16,41.98
3V3_MOS_S on TOP (solid shape): 166.55,47.9 166.55,46.81 166.42,46.68 162.75,46.68 162.62,46.81 162.62,47.9 162.7,47.97 166.47,47.97
3V3_MOS_S on TOP (solid shape): 128.5,30.8 128.5,30.25 131.5,27.25 141.48,27.25 142.32,28.09 142.32,30.17 142.4,30.24 143.29,30.24 143.42,30.12 143.42,27.61 141.94,26.13 131.12,26.13 127.31,29.94 127.31,31.01 127.41,31.11 128.19,31.11
3V3_MOS_S on BOTTOM (solid shape): 157.18,45.94 160.69,45.94 162.75,48 163,48 163.23,47.77 163.23,46.88 163.03,46.69 161.22,44.88 156.6,44.88 152.74,48.74 137.68,48.74 135.13,46.19 135.13,45.73 134.92,45.52 131.77,45.52 128.48,42.23 128.48,29.75 128.32,29.58 127.26,29.58 127.06,29.79 127.06,35.02 127.05,35.02 127.05,35.75 126.47,36.34 123.69,36.34 123.16,36.87 123.16,37.88 123.44,38.17 126.77,38.17 127.06,38.46 127.06,42.54 130.79,46.27 130.79,46.27 131.22,46.7 133.97,46.7 137.12,49.85 153.27,49.85
3V3_MOS_T on TOP (solid shape): 40.6,41.75 40.6,40.38 40.88,40.1 43.6,40.1 43.73,39.97 43.73,39.46 43.6,39.34 41.19,39.34 41.06,39.21 41.06,34.89 40.93,34.77 40.04,34.77 39.92,34.89 39.92,41.78 39.99,41.85 40.5,41.85
3V3_MOS_T on TOP (solid shape): 13.7,28.97 13.7,26.94 15.05,25.6 31.2,25.6 31.92,26.31 31.92,27.35 34.62,27.35 34.62,27.54 34.36,27.54 34.36,27.35 31.92,27.35 31.92,29.3 32.04,29.43 33.31,29.43 33.44,29.3 33.44,28.9 34.38,27.96 34.96,27.96 35.78,27.15 43.47,27.15 43.6,27.02 43.6,24.63 43.37,24.4 14.42,24.4 12.47,26.35 12.47,29.43 12.7,29.66 13.02,29.66
3V3_MOS_T on BOTTOM (solid shape): 40.81,36.16 40.81,26 40.58,25.77 39.99,25.77 39.79,25.98 39.79,36.16 39.92,36.29 40.68,36.29
3V3_MOS_T on BOTTOM (solid shape): 16.09,39.31 16.09,38.93 15.81,38.65 15.28,38.65 13.91,37.28 13.91,28.49 13.73,28.31 12.56,28.31 12.33,28.54 12.33,29.86 12.36,29.89 12.36,36.12 12.06,36.42 8.42,36.42 8.17,36.67 8.17,37.6 8.64,38.07 12.99,38.07 14.54,39.62 15.79,39.62
3V3_RF on TOP (solid shape): 164.88,59.1 164.88,54.2 166.57,52.5 166.57,49.24 166.52,49.19 164.9,49.19 164.69,49.4 162.92,49.4 162.34,48.81 157.31,48.81 157.18,48.94 157.18,50.41 157.34,50.56 161.27,50.56 162.03,51.33 162.03,53.03 163.48,54.48 163.48,59 163.66,59.18 164.8,59.18
5V0_MOS_C on TOP (solid shape): 68.93,33.78 68.93,27.37 77.44,18.87 100.3,18.87 105.53,24.1 105.53,24.76 105.66,24.89 107.1,24.89 107.31,24.68 107.31,23.21 101.14,17.04 76.75,17.04 67.53,26.26 67.53,33.15 66.8,33.88 66.17,33.88 65.66,34.38 65.66,35.15 66.17,35.65 67.06,35.65
5V0_MOS_S on TOP (solid shape): 165.68,63.58 165.68,62.39 164.83,61.54 163.58,61.54 163.51,61.61 163.51,62.53 163.64,62.66 164.04,62.66 164.27,62.88 164.27,63.7 164.32,63.75 165.51,63.75
5V0_MOS_S on TOP (solid shape): 126.54,33.34 126.54,28.34 126.99,27.9 126.99,27.81 127.08,27.81 128.41,26.47 128.41,26.3 128.42,26.28 128.42,17.42 132.54,13.3 141.15,13.3 141.45,13.61 141.45,15.94 141.55,16.05 142.67,16.05 142.75,15.97 142.75,11.8 142.63,11.68 131.94,11.68 126.82,16.79 126.82,26.08 126.7,26.2 126.7,26.23 125.02,27.91 125.02,33.04 124.9,33.16 124.9,33.19 124.87,33.19 124.18,33.88 123.47,33.88 123.16,34.18 123.16,35.15 123.6,35.58 124.31,35.58
5V0_MOS_S on BOTTOM (solid shape): 168.99,60.24 168.99,21.06 166.42,18.48 165.02,18.48 158.29,11.75 140.8,11.75 140.6,11.96 140.6,12.97 140.72,13.1 141.21,13.1 141.49,12.82 157.73,12.82 164.61,19.7 166.06,19.7 167.94,21.58 167.94,40.32 167.95,40.33 167.95,59.66 165.06,62.55 165.06,63.67 165.16,63.77 165.46,63.77
12V0_MOS_S on TOP (solid shape): 124.85,32.83 124.85,27.9 126.58,26.17 126.58,16.86 132.04,11.4 147.53,11.4 148.14,12.01 148.14,16.1 148.34,16.3 153.96,16.3 154.11,16.15 156.67,16.15 157.61,17.09 158.44,17.09 159.04,17.68 159.04,19.48 159.08,19.51 159.4,19.51 159.43,19.48 159.43,17.53 159.43,17.53 159.43,17.29 158.81,16.67 158.31,16.67 158.13,16.5 158.13,15.99 158.09,15.96 157.41,15.96 157.41,15.71 156.04,14.34 150.12,14.34 149.79,14.01 149.79,11.17 148.42,9.8 131.48,9.8 125.03,16.25 125.03,24.53 125.02,24.53 125.02,25.24 124.97,25.29 124.74,25.67 124.36,25.9 123.11,27.15 123.11,32.99 123.19,33.06 124.61,33.06
GND on TOP (solid shape): 28.49,61.82 28.49,59.53 28.36,59.4 26.07,59.4 25.95,59.53 25.95,61.82 26.07,61.94 28.36,61.94
GND on TOP (solid shape): 91.93,37.11 91.93,34.07 91.8,33.94 88.76,33.94 88.63,34.07 88.63,37.11 88.76,37.24 91.8,37.24
GND on TOP (solid shape): 143.11,39.36 143.11,35.55 143.04,35.48 139.33,35.48 139.25,35.55 139.25,39.41 139.35,39.52 142.96,39.52
GND on TOP (solid shape): 25.41,53.69 26.2,53.69 26.33,53.56 26.33,52.16 26.2,52.04 22.26,52.04 21.91,52.39 21.91,53.79 22.19,54.07 25.03,54.07
GND on TOP (solid shape): 89.75,64.49 89.75,61.49 89.64,61.39 86.44,61.39 86.34,61.49 86.34,64.51 86.52,64.69 89.54,64.69
GND on TOP (solid shape): 152.56,65.35 152.56,63.29 152,62.73 150.81,62.73 150.68,62.86 150.68,63.34 151.11,63.77 151.11,65.8 151.21,65.91 152,65.91
GND on TOP (solid shape): 94.78,65.2 94.78,64.05 94.83,64.05 94.83,61.06 93.1,61.06 93.05,61.11 93.05,62.11 92.75,62.42 92.75,62.66 93.58,62.66 93.58,63.11 93.12,63.11 93.12,62.66 92.75,62.66 92.75,63.7 93.61,63.7 93.61,64.1 93.07,64.1 93.07,63.7 92.75,63.7 92.75,64.71 93.56,64.71 93.56,65.15 93.05,65.15 93.05,64.71 92.75,64.71 92.75,65.06 92.99,65.3 94.67,65.3
GND on TOP (solid shape): 88,31.51 88.01,31.52 88.03,31.53 88.06,31.54 88.09,31.53 88.12,31.52 88.14,31.5 88.16,31.48 88.17,31.45 88.17,31.43 88.17,30.97 88.98,30.97 89.01,30.96 89.03,30.95 89.03,30.92 89.03,30.4 88.37,29.74 86.48,29.74 86.46,29.74 86.44,29.75 86.41,29.77 86.39,29.79 86.38,29.82 86.38,29.85 86.38,29.88 86.4,29.91 86.41,29.92 86.75,30.25 88.52,30.25 88.52,30.43 88.29,30.43 88.29,30.25 86.75,30.25
GND on TOP (solid shape): 138.46,66.46 138.47,66.46 138.51,66.42 141.33,66.42 141.39,66.36 141.39,66.09 141.28,65.98 137.32,65.98 134.8,63.46 134.8,51.99 140.34,46.45 140.34,41.4 140.31,41.4 140.28,41.42 140,41.51 139.73,41.38 139.7,41.35 139.65,41.34 139.65,46.27 134.23,51.7 134.23,63.71 137.06,66.54 138.38,66.54
GND on TOP (solid shape): 91.75,59.46 91.75,57.82 91.77,57.82 91.8,57.79 91.8,57.58 91.7,57.47 91.7,50.04 96.89,44.85 96.89,37.69 96.65,37.45 94.11,37.45 94.11,36.89 94.1,36.88 94.1,36.8 93.83,36.53 93.36,36.53 93.24,36.65 93.24,37.66 93.11,37.79 92.45,37.79 92.35,37.89 92.35,38.5 92.02,38.83 92.02,38.96 92.02,38.96 92.02,39.23 92.92,40.13 92.92,48.33 90,51.25 90,53.97 90.56,53.97 90.56,56.76 91.3,56.76 91.3,57.04 90.97,57.04 90.97,56.76 90.56,56.76 90.56,57.2 91.3,57.2 91.3,57.53 90.97,57.53 90.97,57.2 90.56,57.2 90.56,57.6 90.54,57.6 90.51,57.63 90.51,59.38 90.07,59.38 90.02,59.43 90.02,59.74 90.11,59.82 90.11,60.22 90.99,60.22
GND on TOP (solid shape): 91.19,30.09 91.19,29.86 90.31,28.98 89.42,28.09 84.9,28.09 84.14,27.33 84.06,27.33 84.02,27.35 84.01,27.38 84.01,27.56 83.09,27.56 83.09,27.37 83.09,27.35 83.07,27.33 82.91,27.33 82.89,27.35 82.89,27.37 82.89,27.56 81.16,27.56 81.16,27.38 81.15,27.35 81.11,27.33 77.68,27.33 76.41,28.6 76.38,28.71 76.48,28.78 80.98,28.78 81.02,28.76 81.03,28.73 81.03,28.66 83.02,28.66 83.02,28.73 83.03,28.76 83.07,28.78 89.48,28.78 89.54,28.78 90.62,29.86 90.62,30.16 90.66,30.2 91.09,30.2
GND on TOP (solid shape): 138.48,64.2 138.48,61.7 136.35,59.57 136.35,59.56 136.31,59.52 136.31,52.48 142.91,45.88 142.91,44.44 142.88,44.42 142.36,44.42 142.36,45.11 142.34,45.78 141.72,45.52 141.68,45.47 141.68,44.42 141.64,44.42 141.64,43.5 141.69,43.5 141.69,42.7 141.67,42.67 141.51,42.51 141.33,42.51 141.31,42.54 141.31,42.97 141.31,42.97 141.31,44.44 141.31,44.44 141.31,46.85 135.75,52.41 135.75,62.6 137.55,64.4 138.29,64.4
GND on TOP (solid shape): 138.39,68.77 138.39,68.56 138.2,68.38 137.43,68.38 133.26,64.21 133.26,51.29 138.69,45.87 138.69,41.17 138.63,41.11 138.63,40.28 138.62,40.28 137.79,40.28 137.65,40.42 137.65,42.59 137.27,42.97 137.27,43.41 137.27,43.78 137.46,43.97 137.48,43.96 137.54,43.95 137.6,43.94 137.65,43.95 137.71,43.96 137.76,43.98 137.81,44.01 137.85,44.05 137.89,44.09 137.93,44.13 137.95,44.18 137.97,44.23 137.99,44.29 137.99,44.35 137.99,44.4 137.98,44.46 137.96,44.51 137.93,44.56 137.9,44.61 137.86,44.65 137.82,44.69 137.77,44.71 137.72,44.74 137.66,44.75 137.61,44.76 137.55,44.76 137.5,44.75 137.44,44.73 137.39,44.71 137.37,44.7 137.21,44.7 136.79,44.27 136.56,44.27 136.56,44.27 136.1,44.27 136.1,44.27 136.05,44.27 136.05,44.42 136.2,44.42 136.2,45.33 135.29,45.33 135.28,45.25 135.27,45.23 135.24,45.2 134.96,45.48 134.96,45.75 136.13,45.75 136.13,46.02 135.87,46.02 135.87,45.75 134.96,45.75 134.96,48.81 132.67,51.1 132.67,64.43 137.2,68.96 138.19,68.96
GND on TOP (solid shape): 49.77,50.62 49.77,49.07 49.7,48.98 48.47,49.33 47.8,48.38 47.8,48 48.47,47.05 49.7,47.41 49.77,47.31 49.77,44.75 49.53,44.75 49.53,44.8 48.12,44.8 46.67,46.25 46.67,47.1 47.17,47.1 47.17,49.28 46.19,49.28 44.27,51.21 44.25,51.32 44.34,51.38 49.02,51.38
GND on TOP (solid shape): outline of 104 points within 24.65,40.84 30.34,58.03
GND on TOP (solid shape): outline of 131 points within 15.75,40.96 24.68,63.63
GND on TOP (solid shape): outline of 174 points within 20.33,41.46 27.12,61.16
GND on TOP (solid shape): outline of 250 points within 0.79,75.6 8.79,83.6
GND on TOP (solid shape): outline of 250 points within 0.79,8.79 8.79,16.8
GND on TOP (solid shape): outline of 250 points within 46.51,75.6 54.51,83.6
GND on TOP (solid shape): outline of 250 points within 46.51,8.79 54.51,16.8
GND on TOP (solid shape): outline of 250 points within 58.23,75.6 66.23,83.6
GND on TOP (solid shape): outline of 250 points within 58.23,8.79 66.23,16.8
GND on TOP (solid shape): outline of 250 points within 103.95,75.6 111.95,83.6
GND on TOP (solid shape): outline of 250 points within 103.95,8.79 111.95,16.8
GND on TOP (solid shape): outline of 250 points within 115.67,75.6 123.67,83.6
GND on TOP (solid shape): outline of 250 points within 115.67,8.79 123.67,16.8
GND on TOP (solid shape): outline of 250 points within 161.39,75.6 169.39,83.6
GND on TOP (solid shape): outline of 250 points within 161.39,8.79 169.39,16.8
GND on TOP (solid shape): outline of 342 points within 28.49,27.73 49.77,69.6
GND on TOP (solid shape): outline of 424 points within 82.45,21.71 104.23,60.23
GND on TOP (solid shape): outline of 858 points within 137.09,32.11 168.18,72.59
GND on TOP (solid shape): outline of 3611 points within 0.51,8.6 54.93,83.79
GND on TOP (solid shape): outline of 4073 points within 115.39,8.6 169.81,83.79
GND on TOP (solid shape): outline of 5243 points within 57.95,8.6 112.37,83.79
GND on BOTTOM (solid shape): outline of 250 points within 0.79,75.6 8.79,83.6
GND on BOTTOM (solid shape): outline of 250 points within 0.79,8.79 8.79,16.8
GND on BOTTOM (solid shape): outline of 250 points within 46.51,75.6 54.51,83.6
GND on BOTTOM (solid shape): outline of 250 points within 46.51,8.79 54.51,16.8
GND on BOTTOM (solid shape): outline of 250 points within 58.23,75.6 66.23,83.6
GND on BOTTOM (solid shape): outline of 250 points within 58.23,8.79 66.23,16.8
GND on BOTTOM (solid shape): outline of 250 points within 103.95,75.6 111.95,83.6
GND on BOTTOM (solid shape): outline of 250 points within 103.95,8.79 111.95,16.8
GND on BOTTOM (solid shape): outline of 250 points within 115.67,75.6 123.67,83.6
GND on BOTTOM (solid shape): outline of 250 points within 115.67,8.79 123.67,16.8
GND on BOTTOM (solid shape): outline of 250 points within 161.39,75.6 169.39,83.6
GND on BOTTOM (solid shape): outline of 250 points within 161.39,8.79 169.39,16.8
GND on BOTTOM (solid shape): outline of 4830 points within 0.51,8.6 54.93,83.79
GND on BOTTOM (solid shape): outline of 4975 points within 57.95,8.6 112.37,83.79
GND on BOTTOM (solid shape): outline of 5110 points within 115.39,8.6 169.81,83.79
$3N444 on TOP (solid shape): 142.78,24.58 142.78,18.41 140.52,16.15 140.52,13.94 140.47,13.89 139.2,13.89 139.15,13.94 139.15,16.6 136.05,19.7 133.61,19.7 133.56,19.75 133.56,24.71 133.61,24.76 142.6,24.76
$3N444 on BOTTOM (solid shape): 142.55,24.22 142.55,18.74 142.53,18.71 137.27,18.71 137.24,18.74 137.24,24.2 137.3,24.25 142.53,24.25
$4N629 on TOP (solid shape): 164.85,61 164.85,59.96 164.68,59.78 162.75,59.78 162.44,59.48 162.44,57.12 162.39,57.07 160.76,57.07 160.64,57.19 160.64,59.12 160.05,59.71 160.05,60.22 160.1,60.27 160.82,60.27 160.99,60.45 160.99,61.03 161.1,61.13 164.73,61.13
$4N844 on TOP (solid shape): 158.78,25.85 158.78,23.64 158.76,23.62 158.43,23.62 158.4,23.64 158.4,25.34 158.25,25.49 157.62,25.49 156.9,24.78 156.9,21.84 154.19,19.12 148.29,19.12 148.19,19.22 148.19,21.48 148.37,21.66 153.32,21.66 154.52,22.85 154.52,24.71 156.22,26.41 158.22,26.41
$4N851 on TOP (solid shape): 160.18,31.06 160.18,25.77 160.1,25.7 160.1,23.64 160.08,23.62 159.72,23.62 159.7,23.64 159.7,25.55 159.62,25.62 159.62,26.66 159.47,26.82 158.5,26.82 158.28,26.59 157.03,26.59 156.95,26.66 156.95,29.2 156.73,29.43 154.4,29.43 154.24,29.27 154.1,29.27 154.1,29.12 153.97,29 153.97,28.92 153.96,28.91 153.96,26.13 153.91,26.08 151.98,26.08 151.93,26.13 151.93,29.67 152.04,29.79 152.48,29.79 155.17,32.48 158.76,32.48
$4N859 on TOP (solid shape): 150.83,29.74 150.83,26.18 152.31,24.71 152.31,22.57 152.18,22.45 149.44,22.45 147.58,24.3 145.78,24.3 145.5,24.58 145.5,26.43 148.95,29.89 150.68,29.89
$4N880 on TOP (solid shape): 163.77,40.05 163.77,31.49 162.16,29.89 162.16,27.3 161.53,26.66 161.53,26.13 160.74,25.34 160.74,23.64 160.71,23.62 160.38,23.62 160.36,23.64 160.36,31.31 159.98,31.69 159.98,33.98 159.52,34.44 156.75,34.44 156.37,34.82 156.37,40.4 156.7,40.73 163.08,40.73
$5N881 on TOP (solid shape): 45.94,44.11 45.94,42.76 48.16,40.55 48.16,39.13 48.11,39.08 45.25,39.08 45.13,39.21 45.13,40.04 45.69,40.61 45.69,41.14 44.63,42.21 44.63,43.35 44.2,43.78 39.16,43.78 39.03,43.91 39.03,44.8 39.16,44.93 45.12,44.93
$7N237 on TOP (solid shape): 90.34,48.23 90.34,46.81 90.19,46.65 85.37,46.65 85.18,46.47 85.18,45.18 84.96,44.96 84.25,44.96 84.24,44.95 82.19,44.95 80.87,46.27 76.67,46.27 76.63,46.32 76.63,47.52 76.74,47.64 76.74,47.64 76.86,47.76 81.65,47.76 82.15,48.27 88.38,48.27 88.38,48.5 88.16,48.5 88.16,48.27 82.15,48.27 82.17,48.29 87.77,48.29 87.77,48.52 87.59,48.52 87.59,48.29 82.17,48.29 82.82,48.94 89.63,48.94
$8N485 on TOP (solid shape): 109.25,38.77 109.25,34.04 107.33,32.12 107.33,25.57 107.18,25.42 105.61,25.42 105.5,25.52 105.5,32.73 107.31,34.54 107.31,35.47 107.95,35.47 107.95,35.65 107.74,35.65 107.74,35.47 107.31,35.47 107.31,38.75 107.54,38.98 109.04,38.98

Small or netless copper shapes (teardrops, artwork), in the pictures only: 2 on TOP

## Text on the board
Ref Des/Silkscreen Top: HI3137V100+MXL603 | HI3130V200+TDA18250BHN | HI3136V100+AV2012
User.13: FIGURE | SIZE | 10.0 | 12.0 | 32.0 | 35.0 | 45.0 | 24.0 | 138.0 | 70.0x40.0 | 100.0x40.0 | 180.0x50.0 | DRILL CHART: TOP to BOTTOM | ALL UNITS ARE IN MILS | TOLERANCE | +3.0/-3.0 | +0.0/-0.0 | +2.0/-2.0 | PLATED | NON-PLATED | QTY | 3903 | 9 | 96 | 2 | 8 | 4 | 78 | 6 | 60 | 12
